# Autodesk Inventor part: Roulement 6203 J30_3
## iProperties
Author: Administrateur
Created: 2004-01
Part Number: Roulement 6203 J30_3
Material: Par défaut
Document SubType Name: Modélisation
Designer: Administrateur
Control State: 0
Master: False
Checked Out: False
PropertySet Name: Design Tracking Control
Shininess: 20.0
Angle Display Precision: 2
Document Length Units: 11269
Document Angle Units: 11283
Document Time Units: 11279
Document Mass Units: 11290
Document Length Units Precision: 3
Document Angle Units Precision: 2
Compacted: False
PropertySet Name: _Private Model Information
Density: 0.0
Volumn: 0.0
Area: 0.0
PropertySet Name: Model Information
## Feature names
1. Base1
